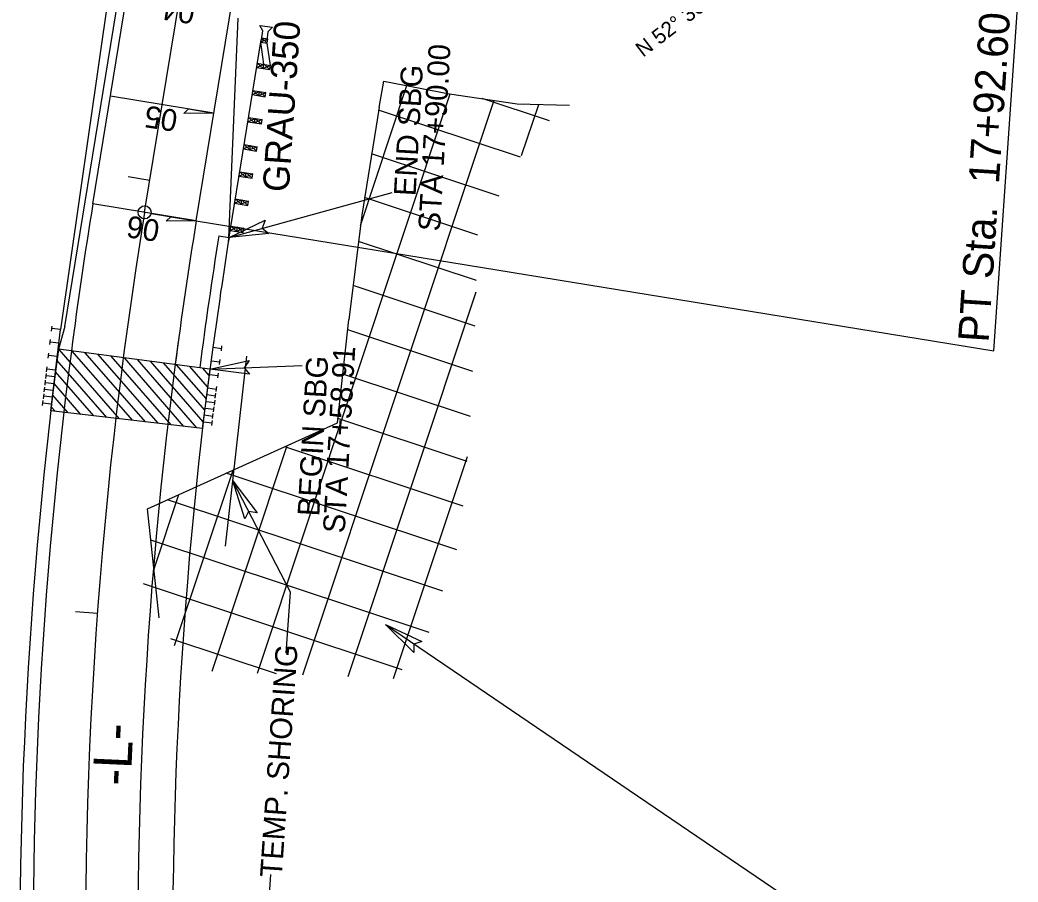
# Model space of a CAD drawing. Extents: x 2599146 to 2600072, y 728518 to 730269.
# Drawn here: x 2599425.7 to 2599654.4, y 729246.4 to 729444 of the extents above; entities that cross this region are included whole.
import ezdxf

# ---------------------------------------------------------------- set-up
doc = ezdxf.new("R2010")
doc.units = 0
for name, color, linetype in [('Default', 7, 'Continuous'), ('Prop Conc Shoulder Berm Gutter', 7, 'Continuous'), ('Prop Dimension', 7, 'Continuous'), ('Prop Dimension Text', 7, 'Continuous'), ('Prop EOT', 7, 'Continuous'), ('Prop Guardrail', 7, 'Continuous'), ('Prop Guardrail Anchor Unit CELL', 7, 'Continuous'), ('Prop Horizontal Alignment', 7, 'Continuous'), ('Prop Horizontal Alignment Direction Label', 7, 'Continuous'), ('Prop Horizontal Alignment Station Label', 7, 'Continuous'), ('Prop Horizontal Alignment Tick Small', 7, 'Continuous'), ('Prop Lane Lines', 7, 'Continuous'), ('Prop Roadway Bridge', 7, 'Continuous'), ('Prop SS Cut Line', 7, 'Continuous'), ('Prop Structure Anchor Unit CELL', 7, 'Continuous'), ('Prop Superelevation Label', 7, 'Continuous'), ('Prop Temporary Shoring', 7, 'Continuous'), ('Prop Temporary Shoring Leader Line', 7, 'Continuous'), ('Prop Temporary Shoring Text', 7, 'Continuous'), ('Prop Terminator CELL', 7, 'Continuous')]:
    doc.layers.add(name, color=color, linetype=linetype)

msp = doc.modelspace()

# ---------------------------------------------------------------- linework, layer by layer
at = {"layer": 'Default'}
for p, q in [((2599503.76, 729396.9), (2599514.41, 729428.94)), ((2599508.05, 729423.95), (2599509.11, 729429.95)), ((2599509.11, 729429.95), (2599524.2, 729427.07)), ((2599480.16, 729294.29), (2599524.32, 729427.06)), ((2599524.2, 729427.07), (2599539.65, 729424.78)), ((2599547.06, 729420.85), (2599531.66, 729425.97)), ((2599490.57, 729293.88), (2599534.37, 729425.57)), ((2599508.05, 729423.95), (2599504.05, 729399.27)), ((2599539.65, 729424.78), (2599551.65, 729424.44)), ((2599540.69, 729412.88), (2599544.6, 729424.64)), ((2599540.47, 729412.5), (2599507.93, 729423.32)), ((2599535.53, 729403.6), (2599506.32, 729413.32)), ((2599530.69, 729394.67), (2599504.7, 729403.32)), ((2599504.05, 729399.27), (2599501.11, 729375.28)), ((2599530.38, 729384.24), (2599503.31, 729393.24)), ((2599530.06, 729373.81), (2599502.07, 729383.12)), ((2599500.97, 729293.47), (2599530.3, 729381.64)), ((2599498.48, 729351.63), (2599501.11, 729375.28)), ((2599529.53, 729363.44), (2599500.85, 729372.98)), ((2599528.94, 729353.1), (2599499.72, 729362.82)), ((2599454.94, 729331.96), (2599498.48, 729351.63)), ((2599528.19, 729342.81), (2599498.59, 729352.66)), ((2599469.76, 729294.7), (2599486.97, 729346.43)), ((2599527.3, 729332.57), (2599486.4, 729346.17)), ((2599511.37, 729293.06), (2599528.29, 729343.92)), ((2599461.18, 729300.59), (2599474.57, 729340.83)), ((2599525.81, 729322.53), (2599472.97, 729340.1)), ((2599456.43, 729317.98), (2599462.16, 729335.22)), ((2599522.64, 729313.04), (2599459.53, 729334.03)), ((2599457.61, 729306.93), (2599454.94, 729331.96)), ((2599519.47, 729303.56), (2599455.7, 729324.77)), ((2599513.35, 729295.05), (2599454.05, 729314.78)), ((2599484.49, 729294.12), (2599460.29, 729302.16))]:
    msp.add_line(p, q, dxfattribs=at)
at = {"layer": 'Prop Conc Shoulder Berm Gutter'}
msp.add_line((2599471.33, 729394.52), (2599473.65, 729394.15), dxfattribs=at)
msp.add_arc((2600480.74, 729232.47), 1022.34, 170.87965, 172.59246, dxfattribs=at)
at = {"layer": 'Prop Dimension'}
for p, q in [((2599473.65, 729394.15), (2599511.06, 729404.42)), ((2599469.26, 729363.98), (2599490.44, 729364.77)), ((2599509.48, 729305.39), (2599608.02, 729238.47))]:
    msp.add_line(p, q, dxfattribs=at)
at = {"layer": 'Prop EOT'}
for p, q in [((2599436.03, 729373.71), (2599506.1, 729804.42)), ((2599442.46, 729401.82), (2599508.08, 729804.09)), ((2599466.15, 729397.96), (2599531.76, 729800.23)), ((2599473.64, 729394.15), (2599475.76, 729444.42)), ((2599436.03, 729373.71), (2599434.55, 729368.49))]:
    msp.add_line(p, q, dxfattribs=at)
for radius in [1052, 1028]:
    msp.add_arc((2600480.74, 729232.47), radius, 170.73628, 172.59246, dxfattribs=at)
at = {"layer": 'Prop Guardrail'}
for p, q in [((2599456.82, 729525.22), (2599435.02, 729373.01)), ((2599474.05, 729396.67), (2599474.36, 729398.57))]:
    msp.add_line(p, q, dxfattribs=at)
msp.add_arc((2600485.71, 729233.78), 1024.69, 170.996, 172.42023, dxfattribs=at)
at = {"layer": 'Prop Guardrail Anchor Unit CELL'}
for p, q in [((2599481.36, 729441.45), (2599480.67, 729442.73)), ((2599480.67, 729442.73), (2599483.58, 729442.32)), ((2599483.58, 729442.32), (2599482.57, 729441.27)), ((2599482.55, 729439.66), (2599480.91, 729438.91)), ((2599481.07, 729439.42), (2599481.36, 729441.45)), ((2599481.07, 729439.9), (2599482.55, 729439.66)), ((2599481.07, 729439.9), (2599482.39, 729438.67)), ((2599482.57, 729441.27), (2599482.28, 729439.25)), ((2599482.39, 729438.67), (2599482.55, 729439.66)), ((2599473.51, 729393.25), (2599480.99, 729439.4)), ((2599480.91, 729438.91), (2599482.39, 729438.67)), ((2599481.64, 729433.83), (2599480.91, 729438.91)), ((2599481.67, 729439.33), (2599481.07, 729439.42)), ((2599482.28, 729439.25), (2599481.67, 729439.33)), ((2599482.39, 729438.67), (2599482.47, 729439.16)), ((2599483.15, 729433.58), (2599482.39, 729438.67)), ((2599479.96, 729433.08), (2599481.64, 729433.83)), ((2599479.96, 729433.08), (2599482.99, 729432.59)), ((2599480.12, 729434.07), (2599483.15, 729433.58)), ((2599481.48, 729432.84), (2599480.12, 729434.07)), ((2599481.48, 729432.84), (2599481.64, 729433.83)), ((2599483.15, 729433.58), (2599481.48, 729432.84)), ((2599481.64, 729433.83), (2599482.99, 729432.59)), ((2599482.99, 729432.59), (2599483.15, 729433.58)), ((2599478.96, 729426.86), (2599480.6, 729427.61)), ((2599478.96, 729426.86), (2599481.92, 729426.38)), ((2599479.12, 729427.85), (2599482.08, 729427.37)), ((2599480.44, 729426.62), (2599479.12, 729427.85)), ((2599480.44, 729426.62), (2599480.6, 729427.61)), ((2599482.08, 729427.37), (2599480.44, 729426.62)), ((2599480.6, 729427.61), (2599481.92, 729426.38)), ((2599481.92, 729426.38), (2599482.08, 729427.37)), ((2599477.95, 729420.64), (2599479.66, 729421.38)), ((2599478.11, 729421.63), (2599481.21, 729421.13)), ((2599479.5, 729420.39), (2599478.11, 729421.63)), ((2599479.5, 729420.39), (2599479.66, 729421.38)), ((2599479.66, 729421.38), (2599481.05, 729420.14)), ((2599477.95, 729420.64), (2599481.05, 729420.14)), ((2599481.21, 729421.13), (2599479.5, 729420.39)), ((2599481.05, 729420.14), (2599481.21, 729421.13)), ((2599476.94, 729414.42), (2599477.1, 729415.41)), ((2599476.94, 729414.42), (2599478.6, 729415.17)), ((2599477.1, 729415.41), (2599480.1, 729414.92)), ((2599478.44, 729414.18), (2599477.1, 729415.41)), ((2599478.44, 729414.18), (2599478.6, 729415.17)), ((2599480.1, 729414.92), (2599478.44, 729414.18)), ((2599478.6, 729415.17), (2599479.94, 729413.94)), ((2599479.94, 729413.94), (2599480.1, 729414.92)), ((2599476.94, 729414.42), (2599479.94, 729413.94)), ((2599475.93, 729408.2), (2599477.6, 729408.95)), ((2599475.93, 729408.2), (2599478.94, 729407.71)), ((2599476.09, 729409.19), (2599479.1, 729408.7)), ((2599477.44, 729407.96), (2599476.09, 729409.19)), ((2599477.44, 729407.96), (2599477.6, 729408.95)), ((2599479.1, 729408.7), (2599477.44, 729407.96)), ((2599477.6, 729408.95), (2599478.94, 729407.71)), ((2599478.94, 729407.71), (2599479.1, 729408.7)), ((2599474.92, 729401.98), (2599476.59, 729402.73)), ((2599474.92, 729401.98), (2599477.94, 729401.49)), ((2599475.08, 729402.97), (2599478.1, 729402.48)), ((2599476.43, 729401.74), (2599475.08, 729402.97)), ((2599476.43, 729401.74), (2599476.59, 729402.73)), ((2599478.1, 729402.48), (2599476.43, 729401.74)), ((2599476.59, 729402.73), (2599477.94, 729401.49)), ((2599477.94, 729401.49), (2599478.1, 729402.48)), ((2599473.92, 729395.76), (2599474.08, 729396.75)), ((2599475.56, 729396.51), (2599473.92, 729395.76)), ((2599474.08, 729396.75), (2599477.04, 729396.27)), ((2599474.08, 729396.75), (2599475.56, 729396.51)), ((2599475.4, 729395.52), (2599474.08, 729396.75)), ((2599475.4, 729395.52), (2599475.56, 729396.51)), ((2599477.04, 729396.27), (2599475.4, 729395.52)), ((2599475.56, 729396.51), (2599476.88, 729395.28)), ((2599476.88, 729395.28), (2599477.04, 729396.27)), ((2599473.92, 729395.76), (2599476.88, 729395.28))]:
    msp.add_line(p, q, dxfattribs=at)
at = {"layer": 'Prop Horizontal Alignment'}
msp.add_line((2599454.31, 729399.89), (2599519.92, 729802.16), dxfattribs=at)
msp.add_arc((2600480.74, 729232.47), 1040, 170.73628, 193.57808, dxfattribs=at)
at = {"layer": 'Prop Horizontal Alignment Station Label'}
for p, q in [((2599648.85, 729368.16), (2599654.43, 729449.02)), ((2599455.79, 729399.65), (2599648.85, 729368.16))]:
    msp.add_line(p, q, dxfattribs=at)
msp.add_circle((2599454.31, 729399.89), 1.5, dxfattribs=at)
at = {"layer": 'Prop Horizontal Alignment Tick Small'}
for p, q in [((2599455.5, 729407.19), (2599450.56, 729408)), ((2599443.49, 729307.95), (2599438.5, 729308.32))]:
    msp.add_line(p, q, dxfattribs=at)
at = {"layer": 'Prop Lane Lines'}
for radius, start in [(1028, 172.27238), (1052, 172.59246)]:
    msp.add_arc((2600480.74, 729232.47), radius, start, 182.39886, dxfattribs=at)
at = {"layer": 'Prop Roadway Bridge'}
for p, q in [((2599469.26, 729363.98), (2599434.55, 729368.49)), ((2599448.58, 729352.56), (2599434.72, 729368.47)), ((2599451.53, 729352.22), (2599437.71, 729368.08)), ((2599454.48, 729351.87), (2599440.7, 729367.69)), ((2599457.43, 729351.53), (2599443.69, 729367.3)), ((2599460.38, 729351.19), (2599446.68, 729366.91)), ((2599463.33, 729350.84), (2599449.67, 729366.52)), ((2599445.62, 729352.9), (2599434.23, 729365.99)), ((2599466.28, 729350.5), (2599452.67, 729366.13)), ((2599467.76, 729351.86), (2599455.66, 729365.75)), ((2599468.07, 729354.54), (2599458.65, 729365.36)), ((2599468.4, 729357.21), (2599461.64, 729364.97)), ((2599468.73, 729359.87), (2599464.63, 729364.58)), ((2599469.07, 729362.52), (2599467.62, 729364.19)), ((2599442.67, 729353.25), (2599433.89, 729363.33)), ((2599439.72, 729353.59), (2599433.56, 729360.66)), ((2599436.77, 729353.93), (2599433.24, 729357.99)), ((2599433.82, 729354.28), (2599432.92, 729355.31)), ((2599467.58, 729350.35), (2599432.81, 729354.39))]:
    msp.add_line(p, q, dxfattribs=at)
for radius in [1055, 1020]:
    msp.add_arc((2600480.74, 729232.47), radius, 172.59247, 182.39886, dxfattribs=at)
at = {"layer": 'Prop SS Cut Line'}
msp.add_line((2599454.94, 729331.96), (2599456.5, 729332.62), dxfattribs=at)
at = {"layer": 'Prop Structure Anchor Unit CELL'}
for p, q in [((2599432.96, 729372.68), (2599433.1, 729373.82)), ((2599432.81, 729354.39), (2599435.02, 729373.01)), ((2599435.02, 729373.01), (2599433.03, 729373.25)), ((2599432.6, 729369.58), (2599432.73, 729370.71)), ((2599434.65, 729369.91), (2599432.66, 729370.15)), ((2599467.58, 729350.35), (2599469.98, 729368.95)), ((2599469.98, 729368.95), (2599471.96, 729368.69)), ((2599471.89, 729368.12), (2599472.03, 729369.26)), ((2599432.23, 729366.47), (2599432.36, 729367.61)), ((2599434.28, 729366.81), (2599432.3, 729367.04)), ((2599431.86, 729363.37), (2599432, 729364.51)), ((2599469.58, 729365.85), (2599471.56, 729365.59)), ((2599471.49, 729365.02), (2599471.63, 729366.16)), ((2599431.68, 729361.82), (2599431.81, 729362.96)), ((2599433.73, 729362.15), (2599431.75, 729362.39)), ((2599433.91, 729363.7), (2599431.93, 729363.94)), ((2599469.18, 729362.75), (2599471.16, 729362.49)), ((2599471.09, 729361.92), (2599471.23, 729363.06)), ((2599431.31, 729358.72), (2599431.45, 729359.85)), ((2599431.49, 729360.27), (2599431.63, 729361.4)), ((2599433.55, 729360.6), (2599431.56, 729360.84)), ((2599468.78, 729359.65), (2599470.76, 729359.39)), ((2599470.69, 729358.82), (2599470.83, 729359.96)), ((2599431.13, 729357.16), (2599431.26, 729358.3)), ((2599433.18, 729357.5), (2599431.19, 729357.73)), ((2599433.36, 729359.05), (2599431.38, 729359.28)), ((2599468.58, 729358.1), (2599470.56, 729357.84)), ((2599470.49, 729357.27), (2599470.63, 729358.41)), ((2599430.94, 729355.61), (2599431.08, 729356.75)), ((2599433, 729355.95), (2599431.01, 729356.18)), ((2599468.38, 729356.55), (2599470.36, 729356.29)), ((2599470.09, 729354.17), (2599470.24, 729355.31)), ((2599470.29, 729355.72), (2599470.44, 729356.86)), ((2599467.98, 729353.45), (2599469.96, 729353.19)), ((2599468.18, 729355), (2599470.16, 729354.74)), ((2599469.89, 729352.62), (2599470.04, 729353.76)), ((2599467.78, 729351.9), (2599469.76, 729351.64)), ((2599469.69, 729351.07), (2599469.84, 729352.21))]:
    msp.add_line(p, q, dxfattribs=at)
at = {"layer": 'Prop Superelevation Label'}
for p, q in [((2599470.18, 729422.63), (2599446.49, 729426.5)), ((2599466.15, 729397.96), (2599442.46, 729401.82))]:
    msp.add_line(p, q, dxfattribs=at)
at = {"layer": 'Prop Temporary Shoring'}
msp.add_line((2599472.84, 729323.38), (2599477.71, 729366.89), dxfattribs=at)
at = {"layer": 'Prop Temporary Shoring Leader Line'}
msp.add_line((2599487.72, 729312.81), (2599474.51, 729338.36), dxfattribs=at)
at = {"layer": 'Prop Temporary Shoring Text'}
for p, q in [((2599486.75, 729298.88), (2599487.72, 729312.81)), ((2599481.99, 729229.88), (2599483.25, 729248.1))]:
    msp.add_line(p, q, dxfattribs=at)
msp.add_lwpolyline([(2599477.27, 729329.65), (2599474.51, 729338.36), (2599480.09, 729331.05), (2599478.14, 729331.34)], close=True, dxfattribs=at)
at = {"layer": 'Prop Terminator CELL'}
for points in [[(2599470.18, 729422.63), (2599463.28, 729422.54), (2599464.33, 729423.59)], [(2599466.14, 729397.96), (2599459.24, 729397.83), (2599460.28, 729398.88)], [(2599482.74, 729395.04), (2599473.65, 729394.15), (2599481.95, 729398.09), (2599481.27, 729396.24)], [(2599478.31, 729362.77), (2599469.26, 729363.98), (2599478.24, 729365.92), (2599477.15, 729364.27)], [(2599516, 729298.99), (2599509.48, 729305.39), (2599517.83, 729301.56), (2599515.98, 729300.89)]]:
    msp.add_lwpolyline(points, close=True, dxfattribs=at)

# ---------------------------------------------------------------- texts
at = {"layer": 'Prop Dimension Text'}
for s, p in [('STA 17+90.00', (2599521.98, 729395.44)), ('END SBG', (2599516.39, 729403.53)), ('STA 17+58.91', (2599500.15, 729326.26)), ('BEGIN SBG', (2599494.32, 729330.14))]:
    msp.add_text(s, height=5, rotation=86.7377, dxfattribs=at).set_placement(p)
at = {"layer": 'Prop Horizontal Alignment Direction Label'}
msp.add_text('N 52%%d 30\' 39.7" E', height=3.5, rotation=37.489, dxfattribs=at).set_placement((2599568.52, 729435.31))
at = {"layer": 'Prop Horizontal Alignment Station Label'}
for s, height, rotation, p in [('PT Sta.  17+92.60', 7, 86.2323, (2599647.66, 729369.95)), ('-L-', 8.75, 87.4031, (2599451.1, 729268.33))]:
    msp.add_text(s, height=height, rotation=rotation, dxfattribs=at).set_placement(p)
at = {"layer": 'Prop Structure Anchor Unit CELL'}
msp.add_text('GRAU-350', height=6, rotation=86.0601, dxfattribs=at).set_placement((2599487.32, 729404.4))
at = {"layer": 'Prop Superelevation Label'}
for s, p in [('04', (2599466.13, 729447.9)), ('05', (2599462.12, 729423.25)), ('06', (2599458, 729398.03))]:
    msp.add_text(s, height=5, rotation=171.1283, dxfattribs=at).set_placement(p)
at = {"layer": 'Prop Temporary Shoring Text'}
msp.add_text('TEMP. SHORING', height=5, rotation=86.05, dxfattribs=at).set_placement((2599485.72, 729247.34))

doc.saveas('drawing.dxf')
